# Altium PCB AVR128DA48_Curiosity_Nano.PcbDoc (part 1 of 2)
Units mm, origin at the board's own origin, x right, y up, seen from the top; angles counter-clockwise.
Board outline 83.82 x 20.32 mm, 4 copper layers (Top-Layer, Ground Plane, Power Plane, Bottom Layer), stack 1.59 mm thick; 66 components, 98 nets, 469 pads, 191 vias.
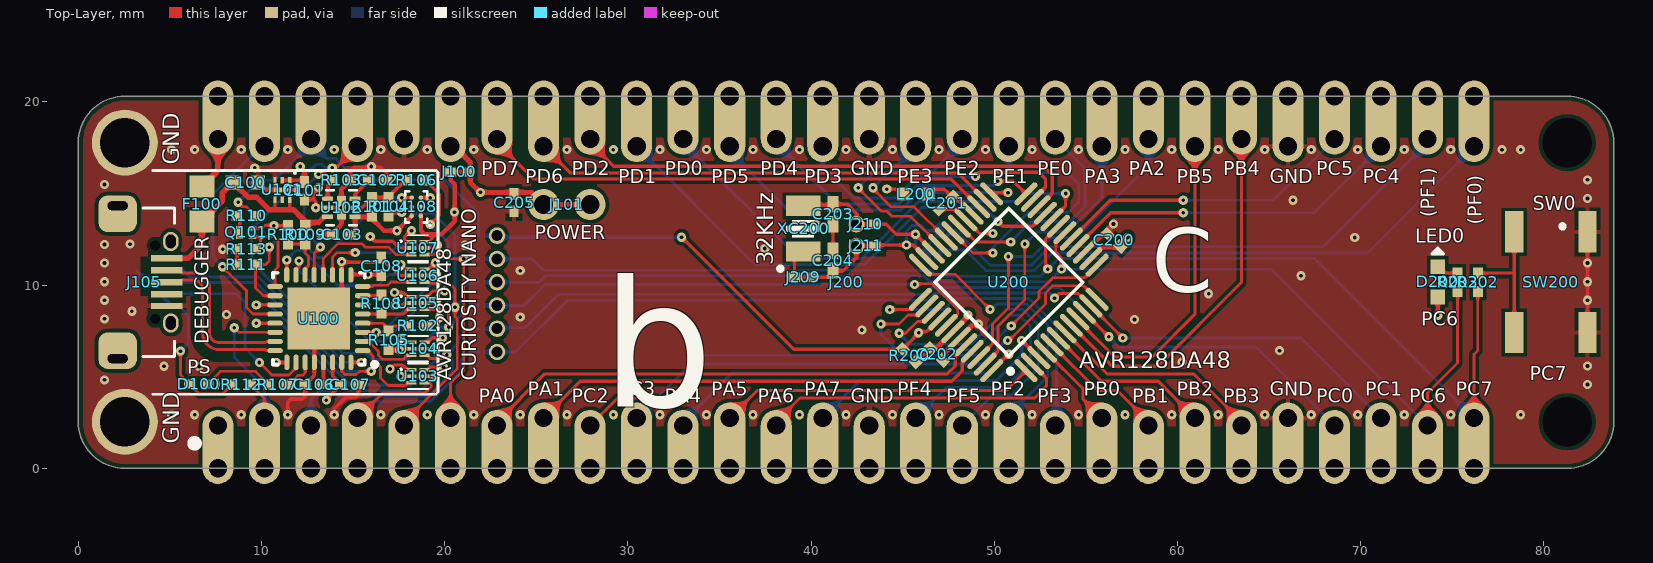
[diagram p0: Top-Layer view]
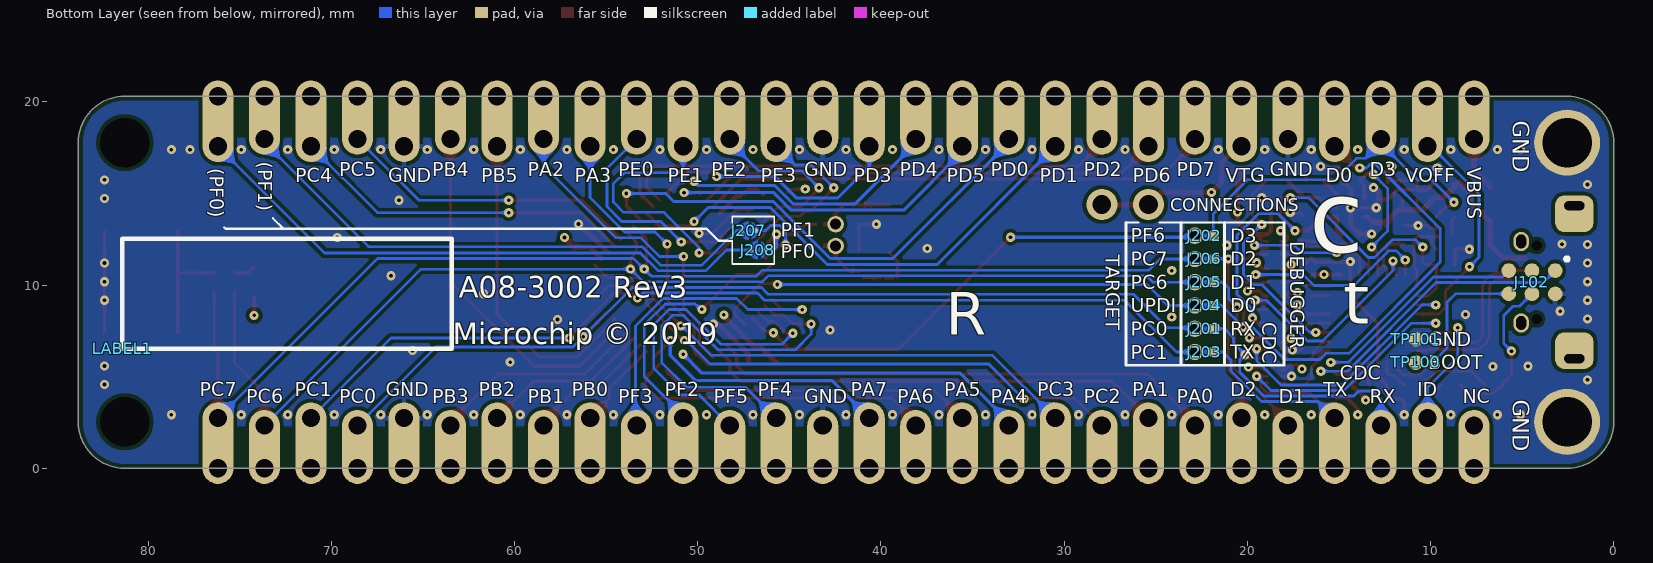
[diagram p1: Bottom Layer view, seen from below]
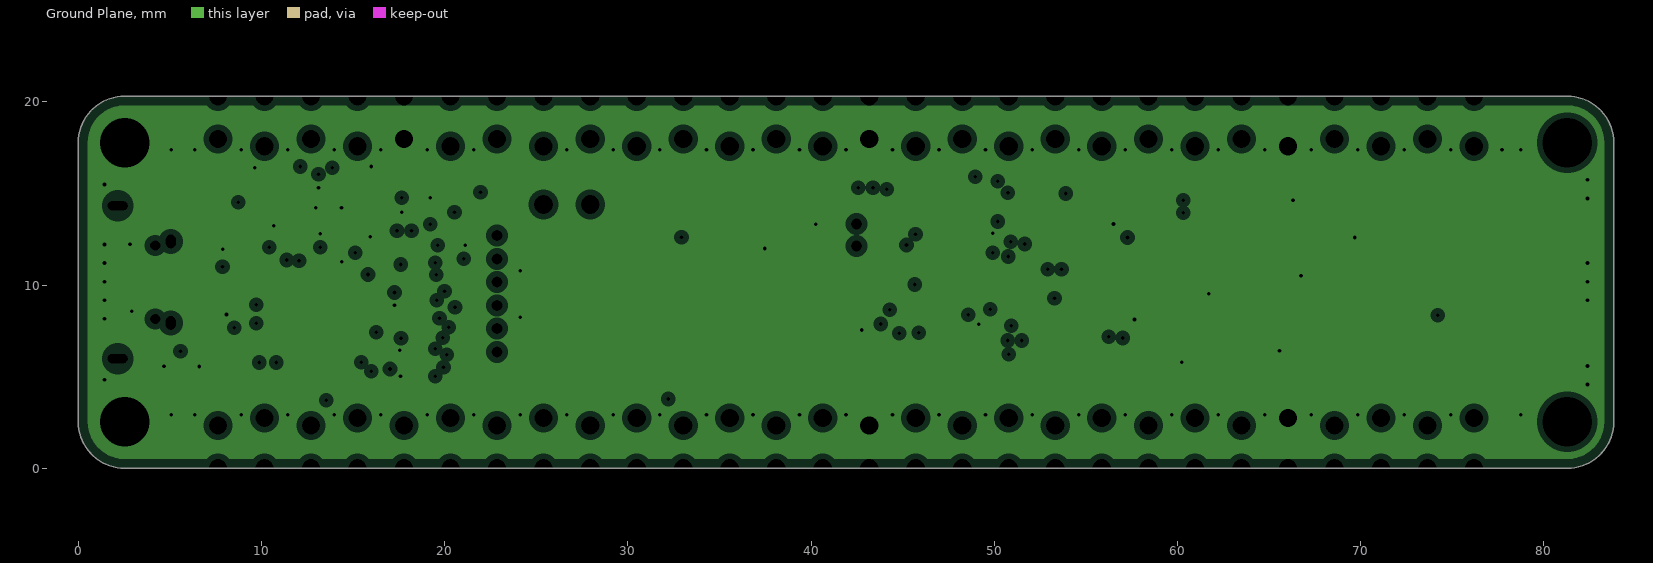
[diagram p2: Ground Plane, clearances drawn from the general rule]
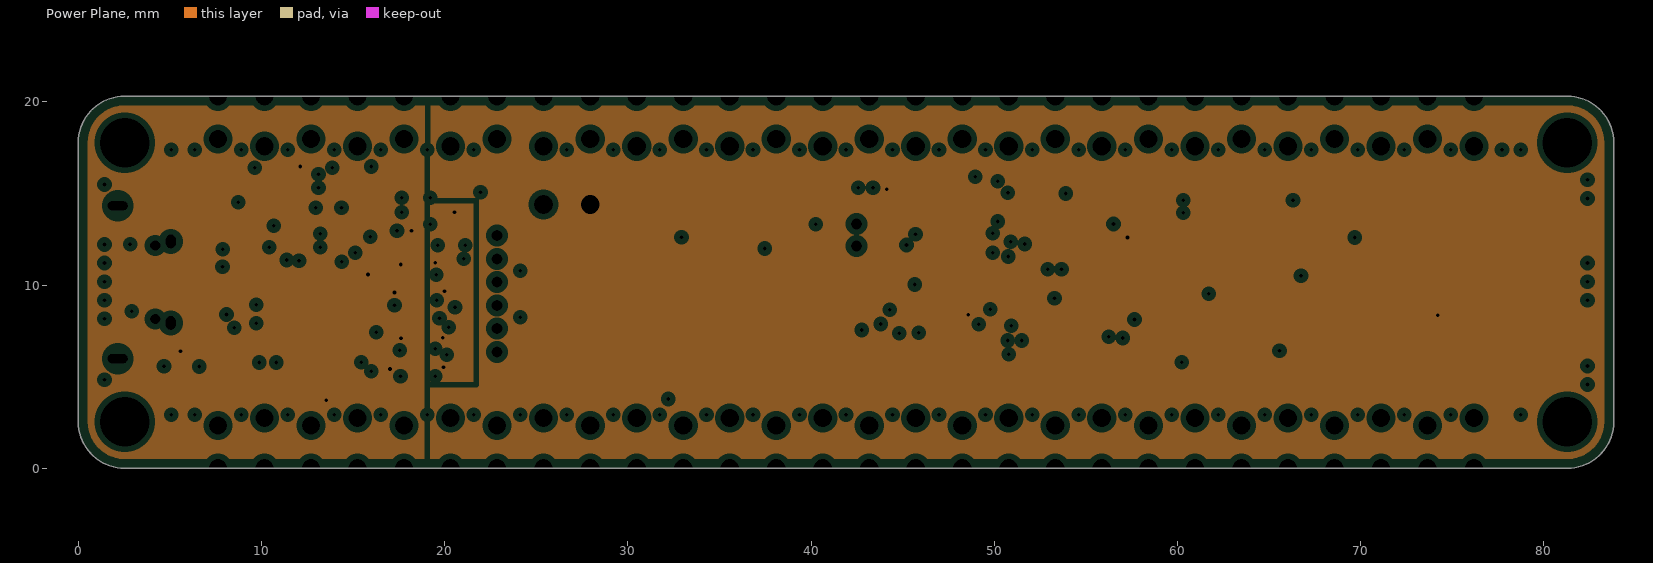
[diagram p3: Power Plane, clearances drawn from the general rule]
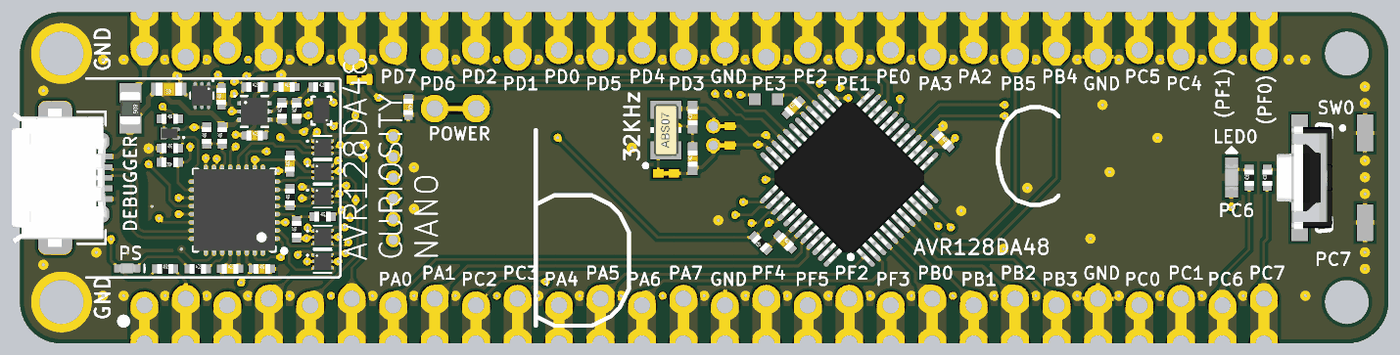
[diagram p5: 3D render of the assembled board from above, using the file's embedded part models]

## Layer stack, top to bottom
Top Solder: solder mask 0.0102, Solder Resist, Dk 3.5
Top-Layer: signal copper 0.035
Dielectric 1: prepreg 0.11, FR-4, Dk 4.2
Ground Plane: plane copper 0.035, net GND
Dielectric 3: core 1.23, Dk 4.2
Power Plane: plane copper 0.035, net (Multiple Nets)
Dielectric 4: prepreg 0.11, Dk 4.2
Bottom Layer: signal copper 0.035
Bottom Solder: solder mask 0.0102, Solder Resist, Dk 3.5

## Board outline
0,2.54 0,17.78 cw(c2.54,17.78) 2.54,20.32 81.28,20.32 cw(c81.28,17.78) 83.82,17.78 83.82,2.54 cw(c81.28,2.54) 81.28,0 2.54,0 cw(c2.54,2.54)

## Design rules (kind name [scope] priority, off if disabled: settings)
AcuteAngle [All] p1: minimum=8.00000000000000E+0001 checktracksonly=TRUE
AssemblyTestPointUsage [All] p1: valid=2 allowmultiple=TRUE
AssemblyTestpoint AssemblyTestpoint_1 [OnBottomLayer and IsComponent] p1: testpointundercomponent=TRUE minsize=0.8 maxsize=2 preferedsize=0.8 minholesize=0 maxholesize=1 preferedholesize=0.25 testpointgrid=0.025 usegrid=FALSE gridtolerance=0 allowsidebottom=TRUE minspacing=1.27 compbodyclearance=1.27
AssemblyTestpoint [All] p2: testpointundercomponent=TRUE minsize=0.8 maxsize=3 preferedsize=0.8 minholesize=0 maxholesize=1 preferedholesize=0.25 testpointgrid=0.025 usegrid=FALSE gridtolerance=0 allowsidebottom=TRUE minspacing=1.27
BoardOutlineClearance BoardOutlineClearance_edge_connector [InComponent('J200') OR InComponent('J201')] p1: gap=0 ignorepadtopadclearanceinfootprint=FALSE
BoardOutlineClearance BoardOutlineClearance_text_top_layer [IsText AND OnTopSilkscreen] p2: gap=0.25 ignorepadtopadclearanceinfootprint=FALSE
BoardOutlineClearance BoardOutlineClearance_FirstPinDot [IsArc AND OnTopSilkscreen] p3: gap=0 ignorepadtopadclearanceinfootprint=FALSE
BoardOutlineClearance [All] p4: gap=0.25 ignorepadtopadclearanceinfootprint=FALSE
Clearance Clearance_Via_in_Pad [IsVia AND (InNet('GND') OR  InNet('BOOT'))] p1: gap=0 ignorepadtopadclearanceinfootprint=FALSE
Clearance Clearance_Poly_Impedance [IsRegion vs InDifferentialPairClass('All Differential Pairs')] p2: gap=0.6 ignorepadtopadclearanceinfootprint=FALSE except(0: Arc-Hole Track-Hole SMDPad-Hole THPad-Hole Via-Hole Fill-Hole Poly-Hole Region-Hole Text-Hole)
Clearance Clearance_Poly [InPoly] p3: gap=0.2 ignorepadtopadclearanceinfootprint=FALSE
Clearance [All] p4: gap=0.15 ignorepadtopadclearanceinfootprint=FALSE
ComponentClearance ComponentClearance_BETWEEN_TESTPOINTS [InComponentClass('Testpoints') vs InComponentClass('Testpoints')] p1: gap=0 collisioncheckmode=3 verticalgap=0 showdistances=FALSE
ComponentClearance ComponentClearance_EDGE [InComponent('J200') or HasFootprint('AP8-01166')] p2: gap=0 collisioncheckmode=3 verticalgap=0 showdistances=FALSE
ComponentClearance ComponentClearance_LABEL [InComponent('LABEL1')] p3: gap=0 collisioncheckmode=3 verticalgap=0 showdistances=FALSE
ComponentClearance [All] p4: gap=0.254 collisioncheckmode=3 verticalgap=0.254 showdistances=TRUE
DiffPairsRouting [All] p1: maxlimit=0.22 minlimit=0.22 mostfreqgap=0.22 toplayer_minwidth=0.16 toplayer_maxwidth=0.16 toplayer_prefwidth=0.16 bottomlayer_minwidth=0.16 bottomlayer_maxwidth=0.16 bottomlayer_prefwidth=0.16 maxuncoupledlength=20
FabricationTestPointUsage TestPointUsage [All] p1: valid=2 allowmultiple=TRUE
FabricationTestpoint Testpoint [All] p1: side=2 testpointundercomponent=TRUE minsize=0.55 maxsize=3 preferedsize=0.8 minholesize=0 maxholesize=1 preferedholesize=0.25 testpointgrid=0 allowsidebottom=TRUE usegrid=FALSE gridtolerance=0 minspacing=1.27
HoleSize [All] p1: absolutevalues=TRUE maxlimit=10 minlimit=0.2 maxpercent=80.000 minpercent=20.000
HoleToHoleClearance HoleToHoleClearance_NPTH [(HoleDiameter > 0) And (PadIsPlated = 'False')] p1: gap=0.25 allowstackedmicrovias=TRUE
HoleToHoleClearance [All] p2: gap=0.3 allowstackedmicrovias=TRUE
MinimumAnnularRing [All] p1: minimumring=0.15
MinimumSolderMaskSliver [All] p1: minsoldermaskwidth=0.08
NetAntennae [Not IsTestpoint] p1: netantennaetolerance=0
PlaneClearance [All] p1: clearance=0.3
PlaneConnect PlaneConnect_VIA [IsVia OR HasPad('Free-666') OR HasPad('Free-EDGE')] p1: planeconnectstyle=Direct reliefexpansion=0.508 reliefentries=4 reliefconductorwidth=0.254 reliefairgap=0.254
PlaneConnect [All] p2: planeconnectstyle=Relief reliefexpansion=0.508 reliefentries=4 reliefconductorwidth=0.254 reliefairgap=0.254
PolygonConnect PolygonConnect_VIA [IsVia OR HasPad('Free-666') OR HasFootprint('AP8-00870')] p1: connectstyle=Direct reliefconductorwidth=0.254 reliefentries=4 polygonreliefangle="90 Angle" airgapwidth=0.254
PolygonConnect [All] p2: connectstyle=Relief reliefconductorwidth=0.254 reliefentries=4 polygonreliefangle="90 Angle" airgapwidth=0.2
RoutingVias [All] p1: holewidth=0.25 width=0.55 viastyle="Through Hole" minholewidth=0.2 minwidth=0.5 maxholewidth=0.5 maxwidth=1
SMDNeckDown [All] p1: percent=98.000
ShortCircuit ShortCircuit_NC_edge_connector [IsPad AND OnLayer('Multi-Layer') AND HasFootprint('AP8-01100') vs IsPad AND OnLayer('Multi-Layer') AND HasFootprint('AP8-01100')] p1: allowed=TRUE
ShortCircuit [All] p2: allowed=FALSE
SilkToSilkClearance SilkToSilkClearance_Text [IsText] p1: silktosilkclearance=0
SilkToSilkClearance [All] p2: silktosilkclearance=0.1
SilkToSolderMaskClearance SilkscreenOverComponentPads_Soldermask [All] p1: minsilkscreentomaskgap=0.12 clearancetoexposedcopper=FALSE
SilkToSolderMaskClearance SilkscreenOverComponentPads_Copper [All] p2: minsilkscreentomaskgap=0.2 clearancetoexposedcopper=TRUE
SolderMaskExpansion SolderMaskTenting [IsVia AND NOT (IsFabTestpoint OR IsAssyTestpoint)] p1: expansion=-1 istentingtop=FALSE
SolderMaskExpansion [All] p2: expansion=0.06 istentingtop=FALSE
ViasUnderSMD ViasUnderSMD_GND [InComponent('U102') And OnLayer('Top-Layer')] p1: allowed=TRUE
ViasUnderSMD ViasUnderSMD_Testpoint [InNet('BOOT') or InNet('GND')] p2: allowed=TRUE
ViasUnderSMD [All] p3: allowed=FALSE
Width Width_Power [InNetClass('Power')] p1: maxlimit=0.5 minlimit=0.175 preferedwidth=0.25
Width [All] p2: maxlimit=10 minlimit=0.15 preferedwidth=0.15
15 further rules are at their usual default settings.

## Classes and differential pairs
differential pair USBD: +USBD_P -USBD_N

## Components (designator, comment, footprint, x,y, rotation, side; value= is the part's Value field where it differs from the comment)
C100 "" AP1-00039 9.118,15.597 r180 top locked value=4.7uF
C101 "Farnell no: 1288200" AP1-00053 12.339,15.15 r90 top locked value=2.2uF
C102 "" AP1-00053 16.34,15.725 r0 top locked value=100n
C103 "" AP1-00053 14.37,12.75 r0 top locked value=2.2uF
C106 "" AP1-00053 12.865,4.575 r0 top locked value=1u
C107 "" AP1-00053 14.815,4.575 r0 top locked value=100n
C108 "" AP1-00053 16.54,11.025 r90 top locked value=100n
C200 "" AP1-00053 56.54,12.446 r315 top locked value=100n
C201 "" AP1-00053 47.371,14.478 r45 top locked value=100n
C202 "" AP1-00053 46.863,6.223 r315 top locked value=100n
C203 "" AP1-00001 41.196,13.874 r90 top locked value=12p
C204 "" AP1-00001 41.196,11.338 r90 top locked value=12p
C205 "" AP1-00053 23.79,14.51 r270 top locked value=2.2uF
D100 "" AP4-00160 6.571,4.6 r180 top locked value="GREEN LED"
D200 "" AP4-00169 74.221,10.181 r270 top locked value="YELLOW LED"
F100 "Farnell no: 1861197" AP2-00002 6.75,14.427 r270 top value=MC36213
J100 "" AP8-00595#1 20.795,16.18 r0 top net-tie value="Closed Link"
J101 "" AP8-01183 26.67,14.402 r0 top locked net-tie value="Closed Link 1x2 100mil header"
J102 "" AP8-00997 5.73,10.16 r0 bottom locked value="Testpoint Array"
J105 "" AP8-01099 2.15,10.16 r270 top locked value=MU-MB0142AB2-269
J200 "" AP8-01100 7.62,10.16 r0 top locked value="CNANO56-pin edge connector"
J201 "" AP8-01166 22.335,7.62 r0 bottom locked net-tie value="Closed Link"
J202 "" AP8-01166 22.335,12.7 r0 bottom locked net-tie value="Closed Link"
J203 "" AP8-01166 22.335,6.35 r0 bottom locked net-tie value="Closed Link"
J204 "" AP8-01166 22.335,8.89 r0 bottom locked net-tie value="Closed Link"
J205 "" AP8-01166 22.335,10.16 r0 bottom locked net-tie value="Closed Link"
J206 "" AP8-01166 22.335,11.43 r0 bottom locked net-tie value="Closed Link"
J207 "" AP9-00172 47.219,12.979 r0 bottom value=SOLDER-STRAP_OPEN
J208 "" AP9-00172 46.719,11.918 r0 bottom value=SOLDER-STRAP_OPEN
J209 "" AP8-00595#2 39.572,10.428 r180 top locked net-tie value="Closed Link"
J210 "" AP8-01166 43,13.326 r180 top net-tie value="Closed Link"
J211 "" AP8-01166 43,12.141 r180 top net-tie value="Closed Link"
L200 "" AP3-00005 45.716,14.976 r0 top value=BLM18PG471SN1
LABEL1 "" AP8-00317 81.425,6.525 r180 bottom locked value="Label PCBA"
Q101 "" AP5-00056 9.15,12.875 r180 top locked value=DMN65D8LFB
R100 "" AP2-00011 11.439,12.75 r90 top locked value=47k
R101 "" AP2-00011 16.04,14.275 r90 top locked value=47k
R102 "" AP2-00011 18.539,7.775 r0 top locked value=47k
R103 "" AP2-00011 14.365,15.725 r0 top locked value=47k
R104 "" AP2-00011 16.94,14.275 r90 top locked value=27k
R105 "" AP2-00011 16.94,6.999 r90 top locked value=47k
R106 "" AP2-00011 18.452,15.725 r0 top locked value=33k
R107 "" AP2-00011 10.89,4.575 r0 top locked value=1k
R108 "" AP2-00011 16.54,8.974 r90 top locked value=1k
R109 "" AP2-00011 12.389,12.75 r90 top locked value=47k
R110 "" AP2-00011 9.175,13.775 r0 top locked value=1k
R111 "" AP2-00011 9.175,11.112 r180 top locked value=47k
R112 "" AP2-00011 8.89,4.575 r0 top locked value=1k
R113 "" AP2-00011 9.175,11.968 r0 top locked value=47k
R200 "" AP2-00011 45.36,6.15 r135 top value=47k
R202 "" AP2-00011 76.405,10.156 r90 top value=1k
R203 "" AP2-00011 75.3,10.156 r90 top value=1k
SW200 "Rating: DC 12V 50mA / Max 0.1 ohm contact resistance" AP8-00137 80.391,10.16 r270 top locked value=TS604VM1-035CR
TP100 "PCB implemented component." AP8-00870 10.81,5.777 r90 bottom locked value="SMD Test point - 0.8mm"
TP101 "PCB implemented component." AP8-00870 10.81,7.047 r90 bottom locked value="SMD Test point - 0.8mm"
U100 "QFN32" AP6-00418 13.13,8.17 r90 top locked value=SAMD21E18A-MUT
U101 "" AP6-00481 11.139,15.2 r270 top locked value=MIC5528-3.3YMT
U102 "Marking code: AAR" AP6-00504 14.365,14.225 r0 top locked value=MIC5353
U103 "" AP6-00505 18.539,5.025 r0 top locked value=74LVC1T45FW4-7
U104 "" AP6-00505 18.539,6.525 r0 top locked value=74LVC1T45FW4-7
U105 "" AP6-00505 18.539,9.025 r0 top locked value=74LVC1T45FW4-7
U106 "" AP6-00505 18.539,10.525 r0 top locked value=74LVC1T45FW4-7
U107 "" AP6-00505 18.539,12.025 r0 top locked value=74LVC1T45FW4-7
U108 "" AP6-00513 18.452,14.275 r180 top locked value=MIC94163
U200 "" AP6-00357 50.8,10.16 r135 top locked value="AVR128DA48 TQFP"
XC200 "" AP7-00069 39.572,13.081 r90 top locked value=32.768kHz

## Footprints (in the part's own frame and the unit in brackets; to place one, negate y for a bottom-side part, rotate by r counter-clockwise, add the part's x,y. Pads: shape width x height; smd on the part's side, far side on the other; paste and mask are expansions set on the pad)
AP1-00001 [mm] "Standard 0402 SMD capacitor footprint"
  rect 0.9x0.6 smd: 1(-0.55,0) 2(0.55,0)
  body extent -0.5,-0.3 0.5,0.3, height 0.2
AP1-00039 [mil] "Capacitor 0603 Hight 0.8mm"
  rect 30x30 smd: 1(-27.5,0) 2(27.5,0)
  body extent -31,-16 32,16, height 12
AP1-00053 [mm] "Chip Capacitor, 2-Leads, Body 1.0x0.5mm, IPC High Density"
  rect 0.65x0.5 smd: 1(-0.475,0) 2(0.475,0)
  body extent -0.5,-0.3 0.5,0.3, height 0.2
AP2-00002 [mm]
  rect 1.2x1.35 smd: 1(-0.95,0) 2(0.95,0)
  body extent -1,-0.62 1,0.63, height 0.78
AP2-00011 [mm] "Chip Resistor, 2-Leads, Body 1,0x0,5mm, IPC High Density"
  rect 0.6x0.55 smd: 1(-0.5,0) 2(0.5,0)
  body extent -0.5,-0.3 0.5,0.3, height 0.2
AP3-00005 [mm]
  rect 0.7x0.7 smd: 1(-0.7,0) 2(0.7,0)
  body extent -0.83,-0.41 0.82,0.41, height 0.8
AP4-00160 [mm] "ROHM SML-P11 0402 LED"
  rect 0.6x0.5 smd: 1(-0.5,0) 2(0.5,0)
  silkscreen extent -1.14,-0.25 -1.05,0.25, body extent -0.5,-0.3 0.5,0.3, height 0.19
AP4-00169 [mm] "ROHM SML-D1x 0603 LED"
  rect 0.8x0.8 smd: 1(-0.825,0) 2(0.825,0)
  silkscreen extent -1.83,-0.3 -1.53,0.3, body extent -0.8,-0.4 0.8,0.4, height 0.54
AP5-00056 [mm] "DFN1006-3/SOT883, 3-Leads, Body 1,050x0,65mm, Pitch 0,35mm"
  oval 0.508x0.229 on Top Paste: 0(-0.4,0.25) 0(-0.4,-0.25)
  rect 0.4x0.25 smd paste-1: 1(-0.35,0.225) 2(-0.35,-0.225)
  rect 0.4x0.7 smd: 3(0.35,0)
  silkscreen extent -0.92,0.2 -0.83,0.3, body extent -0.5,-0.3 0.5,0.3, height 0.49
AP6-00357 [mm]
  oval 1.65x0.3 smd mask+0.05: 1(-4.075,2.75) 2(-4.075,2.25) 3(-4.075,1.75) 4(-4.075,1.25) 5(-4.075,0.75) 6(-4.075,0.25) 7(-4.075,-0.25) 8(-4.075,-0.75) 9(-4.075,-1.25) 10(-4.075,-1.75) 11(-4.075,-2.25) 12(-4.075,-2.75) 25(4.075,-2.75) 26(4.075,-2.25) 27(4.075,-1.75) 28(4.075,-1.25) 29(4.075,-0.75) 30(4.075,-0.25) 31(4.075,0.25) 32(4.075,0.75) 33(4.075,1.25) 34(4.075,1.75) 35(4.075,2.25) 36(4.075,2.75)
  oval 0.3x1.65 smd mask+0.05: 13(-2.75,-4.075) 14(-2.25,-4.075) 15(-1.75,-4.075) 16(-1.25,-4.075) 17(-0.75,-4.075) 18(-0.25,-4.075) 19(0.25,-4.075) 20(0.75,-4.075) 21(1.25,-4.075) 22(1.75,-4.075) 23(2.25,-4.075) 24(2.75,-4.075) 37(2.75,4.075) 38(2.25,4.075) 39(1.75,4.075) 40(1.25,4.075) 41(0.75,4.075) 42(0.25,4.075) 43(-0.25,4.075) 44(-0.75,4.075) 45(-1.25,4.075) 46(-1.75,4.075) 47(-2.25,4.075) 48(-2.75,4.075)
  silkscreen extent -3.62,-2.85 2.85,3.5, body extent -4.5,-4.5 4.5,4.5, height 1.45
AP6-00418 [mm] "MLF-32 solder foot print"
  oval 0.28x0.85 smd paste-0.03 mask+0: 1(-1.746,-2.39) 2(-1.246,-2.39) 3(-0.746,-2.39) 4(-0.246,-2.39) 5(0.254,-2.39) 6(0.754,-2.39) 7(1.254,-2.39) 8(1.754,-2.39) 17(1.754,2.39) 18(1.254,2.39) 19(0.754,2.39) 20(0.254,2.39) 21(-0.246,2.39) 22(-0.746,2.39) 23(-1.246,2.39) 24(-1.746,2.39)
  oval 0.85x0.28 smd paste-0.03 mask+0: 9(2.386,-1.746) 10(2.386,-1.246) 11(2.386,-0.746) 12(2.386,-0.246) 13(2.386,0.254) 14(2.386,0.754) 15(2.386,1.254) 16(2.386,1.754) 25(-2.383,1.746) 26(-2.383,1.246) 27(-2.383,0.746) 28(-2.383,0.246) 29(-2.383,-0.254) 30(-2.383,-0.754) 31(-2.383,-1.254) 32(-2.386,-1.75)
  rect 3.4x3.4 smd paste-1.7 mask+0: 33(0.004,0)
  silkscreen extent -2.62,-3.18 2.5,2.5, body extent -2.55,-2.55 2.55,2.55, height 1
AP6-00481 [mm] "6 Pin 1.2mm X 1.2mm Thin DFN"
  oval 0.483x0.203 on Top Paste: 0(-0.597,0.412) 0(-0.597,0) 0(-0.597,-0.412) 0(0.597,0.412) 0(0.597,0) 0(0.597,-0.412)
  rect 0.35x0.18 smd paste-0.09 mask+0.05: 1(-0.531,0.4) 2(-0.531,0) 3(-0.531,-0.4) 4(0.531,-0.4) 5(0.531,0) 6(0.531,0.4)
  rect 0.28x0.94 smd paste-0.02 mask+0.05: 7(0,0)
  silkscreen extent -0.97,0.64 -0.88,0.74, body extent -0.63,-0.62 0.63,0.63, height 0.6
AP6-00504 [mm] "MLF, 6-Leads, Body 1,60x1,60mm, Pitch 0,50mm, Thermal Pad 1,26x0,33mm, IPC High Density"
  rect 0.6x0.25 smd mask+0.05: 1(-0.75,0.5) 2(-0.75,0) 3(-0.75,-0.5) 4(0.75,-0.5) 5(0.75,0) 6(0.75,0.5)
  rect 0.5x1.26 smd paste-0.1 mask+0.05: 7(0,0)
  silkscreen extent -1.25,-0.95 0.82,1, body extent -0.87,-0.82 0.87,0.82, height 0.55
AP6-00505 [mm] "X2-DFN1010, 6-Leads, Body 1,05x1,05mm, Pitch 0,35mm, IPC High Density"
  oval 0.559x0.178 on Top Paste: 0(-0.375,-0.401) 0(-0.375,0) 0(-0.375,0.401) 0(0.375,-0.401) 0(0.375,0) 0(0.375,0.401)
  rect 0.55x0.2 smd paste-0.1: 1(-0.35,0.35) 2(-0.35,0) 3(-0.35,-0.35) 4(0.35,-0.35) 5(0.35,0) 6(0.35,0.35)
  silkscreen extent -0.97,-0.7 0.55,0.7, body extent -0.53,-0.53 0.53,0.53, height 0.4
AP6-00513 [mm] "BGA, 6-Leads, Body 1,00x1,50mmx0,80mm, Pitch 0,50mm"
  round 0.25 smd mask+0.05: A1(-0.25,0.5) A2(0.25,0.5) B1(-0.25,0) B2(0.25,0) C1(-0.25,-0.5) C2(0.25,-0.5)
  silkscreen extent -0.8,-0.85 0.6,1.05, body extent -0.5,-0.75 0.5,0.75, height 0.8
AP7-00069 [mm]
  rect 1.1x1.9 smd: 1(-1.25,0) 2(1.25,0)
  Top-Layer pour cut-out: -0.6,0.95 -0.6,-0.95 0.6,-0.95 0.6,0.95
  silkscreen extent -2.28,-0.95 0.47,1.35, body extent -1.6,-0.75 1.6,0.75, height 0.89
AP8-00137 [mm]
  rect 2.25x1 smd: 1(-2.75,2) 2(2.75,2) 3(-2.75,-2) 4(2.75,-2)
  silkscreen extent -3.15,0.54 -2.95,0.73, body extent -3.4,-3.21 3.4,3.22, height 3.47
AP8-00317 [mm] "Placement area for 18x6mm sticker"
  silkscreen extent 0,0 18,6
AP8-00595#1 [mm]
  rect 0.65x0.5 smd paste-1: 1(-0.475,0) 2(0.475,0)
  Top-Layer lines w0.254: -0.175,0 0.2,0
AP8-00595#2 [mm]
  rect 0.65x0.5 smd paste-2: 1(-0.475,0) 2(0.475,0)
  Top-Layer lines w0.254: 0.2,0 -0.175,0
AP8-00870 [mil] "TP_SMT_.8mm"
  round 31.5 smd paste-39.37: 1(0,0)
AP8-00997 [mm] "SMT test point array 2x5 0.8mm, Pitch 1.27 mm"
  round 0.8 smd paste-1: 1(-2.54,-0.635) 2(-2.54,0.635) 3(-1.27,-0.635) 4(-1.27,0.635) 5(0,-0.635) 6(0,0.635)
  silkscreen extent -3.28,-1.37 -3.07,-1.17
AP8-01099 [mm] "Micro USB AB connector from Allen Creations. Signals surface mount, shield DIP"
  rrect52% 2x2.1 on Top Paste: 0(-3.69,0) 0(3.69,0)
  rrect100% 1.05x0.84 on Top Paste: 0(-2.225,2.9) 0(2.225,2.9)
  rect 0.35x1.7 smd: 1(-1.3,2.68) 2(-0.65,2.68) 3(0,2.68) 4(0.65,2.68) 5(1.3,2.68)
  rrect52% 2x2.1 hole 0.5 slot 1.1 at 90 deg copper offset 0.437,0: 6(-4.175,0)
  rrect52% 2x2.1 hole 0.5 slot 1.1 at 90 deg copper offset -0.437,0: 7(4.175,0)
  rrect100% 1.05x0.84 hole 0.54 slot 0.75 at 0 deg: 8(-2.225,2.9) 9(2.225,2.9)
  round 0 hole 0.55 unplated: 10(-2,2.05) 11(2,2.05)
  silkscreen extent -4.05,1.38 4.05,3.1, body extent -4.32,-2.65 4.33,3.25, height 2.78
AP8-01100 [mil] "56-pin Header staggered with castellations (for CNANO)"
  round 75 on Top Solder: 0(0,-400) 0(0,400) 0(100,-400) 0(100,400) 0(200,-400) 0(200,400) 0(300,-400) 0(300,400) 0(400,-400) 0(400,400) 0(500,-400) 0(500,400) 0(600,-400) 0(600,400) 0(700,-400) 0(700,400) 0(800,-400) 0(800,400) 0(900,-400) 0(900,400) 0(1000,-400) 0(1000,400) 0(1100,-400) 0(1100,400) 0(1200,-400) 0(1200,400) 0(1300,-400) 0(1300,400) 0(1400,-400) 0(1400,400) 0(1500,-400) 0(1500,400) 0(1600,-400) 0(1600,400) 0(1700,-400) 0(1700,400) 0(1800,-400) 0(1800,400) 0(1900,-400) 0(1900,400) 0(2000,-400) 0(2000,400) 0(2100,-400) 0(2100,400) 0(2200,-400) 0(2200,400) 0(2300,-400) 0(2300,400) 0(2400,-400) 0(2400,400) 0(2500,-400) 0(2500,400) 0(2600,-400) 0(2600,400) 0(2700,-400) 0(2700,400)
  oval 67x155 hole 39.37 copper offset 0,44 mask-20: 1(0,-400) 3(200,-400) 5(400,-400) 7(600,-400) 9(800,-400) 11(1000,-400) 13(1200,-400) 15(1400,-400) 17(1600,-400) 19(1800,-400) 21(2000,-400) 23(2200,-400) 25(2400,-400) 27(2600,-400)
  round 67 hole 39.37 mask+3.94: 1(0,-308) 2(100,-292) 3(200,-308) 4(300,-292) 5(400,-308) 6(500,-292) 7(600,-308) 8(700,-292) 9(800,-308) 10(900,-292) 11(1000,-308) 12(1100,-292) 13(1200,-308) 14(1300,-292) 15(1400,-308) 16(1500,-292) 17(1600,-308) 18(1700,-292) 19(1800,-308) 20(1900,-292) 21(2000,-308) 22(2100,-292) 23(2200,-308) 24(2300,-292) 25(2400,-308) 26(2500,-292) 27(2600,-308) 28(2700,-292) 29(2700,292) 30(2600,308) 31(2500,292) 32(2400,308) 33(2300,292) 34(2200,308) 35(2100,292) 36(2000,308) 37(1900,292) 38(1800,308) 39(1700,292) 40(1600,308) 41(1500,292) 42(1400,308) 43(1300,292) 44(1200,308) 45(1100,292) 46(1000,308) 47(900,292) 48(800,308) 49(700,292) 50(600,308) 51(500,292) 52(400,308) 53(300,292) 54(200,308) 55(100,292) 56(0,308)
  oval 67x171 hole 39.37 copper offset 0,52 mask-20: 2(100,-400) 4(300,-400) 6(500,-400) 8(700,-400) 10(900,-400) 12(1100,-400) 14(1300,-400) 16(1500,-400) 18(1700,-400) 20(1900,-400) 22(2100,-400) 24(2300,-400) 26(2500,-400) 28(2700,-400)
  oval 67x171 hole 39.37 copper offset 0,-52 mask-20: 29(2700,400) 31(2500,400) 33(2300,400) 35(2100,400) 37(1900,400) 39(1700,400) 41(1500,400) 43(1300,400) 45(1100,400) 47(900,400) 49(700,400) 51(500,400) 53(300,400) 55(100,400)
  oval 67x155 hole 39.37 copper offset 0,-44 mask-20: 30(2600,400) 32(2400,400) 34(2200,400) 36(2000,400) 38(1800,400) 40(1600,400) 42(1400,400) 44(1200,400) 46(1000,400) 48(800,400) 50(600,400) 52(400,400) 54(200,400) 56(0,400)
  Multi-Layer pour cut-out: -40,-310 -40,-450 2740,-450 2740,-310
  Multi-Layer pour cut-out: 2740,310 2740,450 -40,450 -40,310
AP8-01166 [mm] "Cut-Strap 0402 with hole"
  rect 0.65x0.5 smd paste-1: 1(-0.475,0)
  round 0.9 hole 0.6 paste-1: 2(0.525,0)
  Top-Layer region: -0.175,0.125 0.175,0.125 0.175,-0.125 -0.175,-0.125
AP8-01183 [mm] "closed link, 100-mil 1 x 2 pin header footprint"
  round 1.7 hole 1.02: 1(-1.27,0) 2(1.27,0)
  Top-Layer lines w0.3: -1.27,0 1.27,0
AP9-00172 [mm]
  round 0.25 smd paste-4 mask-2: 1(-0.375,0) 2(0.375,0)
  round 1.05 on Bottom Solder: 5(0,0)
  Top-Layer region: 0,-0.5 0.217,-0.45 0.391,-0.312 0.487,-0.111 0.487,0.111 0.391,0.312 0.217,0.45 0,0.5 0,0.5 0,0.325 0.25,0.075 0.25,-0.075 0,-0.325
  Top-Layer region: -0.175,-0.468 -0.373,-0.333 -0.485,-0.12 -0.485,0.12 -0.373,0.333 -0.175,0.468 -0.175,0.468 -0.175,0.468 -0.175,0.25 0.075,0 0.075,0 -0.175,-0.25
  body extent -0.25,-0.25 0.25,0.25, height 0.45

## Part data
C100: library part A01-0377, "Ceramic capacitor, SMD 0603, X5R, 10V, 10% (de31036)", Manufacturer="WALSIN Technology Corporation", MPN=0603X475K100CT, TemperatureRange="-55 - +85 deg C", Tolerance=10%
C101: library part A01-0300, "Ceramic capacitor, SMD 0402, X5R, 6.3V, +/-20%", Manufacturer=Kemet, MPN=C0402C225M9PAC, TemperatureRange="-55Â°C to +85Â°C", Tolerance=Â±20%
C102 C107 C108 C200 C201 C202: library part A01-0246, "Ceramic capacitor, SMD 0402, X7R, 16V, +/-10%", Manufacturer=Kemet, MPN=C0402C104K4RACTU, TemperatureRange="-55 - +125 deg C", Tolerance="16V, +/-10%"
C103 C205: library part A01-0493, "CAP CER 2.2UF 10V 10% X5R 0402", Manufacturer=TDK, MPN=C1005X5R1A225K, TemperatureRange="-55 to 85C", Tolerance=+/-10%
C106: library part A01-0286, "Ceramic capacitor, SMD 0402, X5R, 6.3V, +/-10% (de26942)", Manufacturer=Kemet, MPN=C0402C105K9PAC, TemperatureRange="-55 to 85 deg C", Tolerance=+/-10%
C203 C204: library part A01-0016, "Ceramic capacitor, SMD 0402, NP0, 50V, +/-5%", Manufacturer=Kemet, MPN=C0402C120J5GAC7867, TemperatureRange="-55 - +125 deg C", Tolerance="50V, +/-5%"
D100: library part A10-0213, "LED, SMD 0402, Green, Wave length=569nm, 2.1mcd @ (1mA, 1.9Vf)rohm", Manufacturer=ROHM, MPN=SML-P12MTT86R, TemperatureRange="-40 to +85"
D200: library part A10-0218, "LED, SMD 0603, Yellow, Wave length=590nm, 100mcd @ (20mA, 2.2Vf) rohm", Manufacturer=ROHM, MPN=SML-D12Y1WT86, TemperatureRange="-40 to +85"
F100: library part A02-0622, "Resetable PTC fuse, Ih = 0.5A, It = 1.0A, 0805 package", Manufacturer=Multicomp, MPN=MC36213, TemperatureRange="-40°C to + 85°C"
J100 J209: library part A08-1454, "Closed Link 0402"
J101: library part A08-3029, "Closed Link with w/hole for 1x2 100mil header"
J102: library part A08-2568, "10-pin Testpoint Array, 0.8mm Pad, 1.27mm Pitch"
J105: library part A08-2839, "USB micro AB, Surface mount signals and DIP shield", Manufacturer="Allen Creations Corp.", MPN=MU-MB0142AB2-269, TemperatureRange="-30Â°C to +80Â°C"
J200: library part A08-2840, "Curiosity Nano 56-pin edge connector with castellations, 100-mil pitch."
J201 J202 J203 J204 J205 J206 J210 J211: library part A08-2981, "Closed Link 0402 w/50mil hole"
J207 J208: library part A08-2866, "1x1mm, Round Strap, Open, no frame"
L200: library part A03-0035, "SMD RF inductor 0603. Z=470Ohm (@100MHz), Max R(dc)=0.20Ohm, Max current=1A", Manufacturer=Murata, MPN=BLM18PG471SN1, TemperatureRange=-55
LABEL1: library part A09-0611, "PCBA identification label PP Top White Gloss", Manufacturer="ACT Logimark AS", MPN=505462
Q101: library part A05-0180, "N-channel MOSFET, DFN1006-3 (SOT883), 60V, 330mA, 4Ohm", Manufacturer="Diodes Incorporated", MPN=DMN65D8LFB-7, TemperatureRange="-55Â°C to +150Â°C"
R100 R101 R102 R103 R105 R109 R111 R113 R200: library part A02-0252, "Thick film resistor, SMD 0402, 1/16W, 1%", Manufacturer=KOA, MPN=RK73H1ETTP4702F, TemperatureRange="-55 - +125 deg C", Tolerance="1 %"
R104: library part A02-0246, "Thick film resistor, SMD 0402, 1/16W, 1%", Manufacturer=Yageo, MPN=RC0402FR-0727KL, TemperatureRange="-55 - +125 deg C", Tolerance="1 %"
R106: library part A02-0248, "Thick film resistor, SMD 0402, 1/16W, 1%", Manufacturer="ASJ Holdings", MPN=CR10-3302-FK, TemperatureRange="-55 - +125 deg C", Tolerance="1 %"
R107 R108 R110 R112 R202 R203: library part A02-0212, "Thick film resistor, SMD 0402, 1/16W, 1%", Manufacturer="ASJ Holdings", MPN=CR10-1001-FK, TemperatureRange="-55 - +125 deg C", Tolerance="1 %"
SW200: library part A08-2830, "SWITCH, SMD, 260gf, 6.4mm X 6.2mm", Manufacturer="Dailywell Electronics Co.LTD", MPN=TS604VM1-035CR-R, TemperatureRange="-40 - +85 deg C"
TP100 TP101: library part A08-2176, "SMD Test point - 0.8mm"
U100: library part A06-1205, "32-bit RISC MCU 32pin", Manufacturer=Microchip, MPN=ATSAMD21E18A-MUT, TemperatureRange="-40Â°C to +85Â°C"
U101: library part A06-1475, "LDO 3.3V 0.5A 6TDFN", Manufacturer=Microchip, MPN=MIC5528-3.3YMT-T5, TemperatureRange="-40Â°C ~ 125Â°C"
U102: library part A06-1578, "500mA Ultra Low Dropout LDO regulator, 2% accuracy, 1.6x1.6mm MLF", Manufacturer=Microchip, MPN=MIC5353YMT-TR, TemperatureRange="-40Â°C to +125Â°C"
U103 U104 U105 U106 U107: library part A06-1580, "Single-Bit Dual-Supply Transceive, 1.65-5.5 Translation and 3-State Outputs", Manufacturer="Diodes Incorporated", MPN=74LVC1T45FW4-7, TemperatureRange="-40C - 125C"
U108: library part A06-1613, "Loadswitch, Rds(on) = 14.5mohm, 1.0mm x 1.5mm WLCSP, reverse blocking", Manufacturer=Microchip, MPN=MIC94163YCS-TR, TemperatureRange="-40Â°C to +125Â°C"
U200: library part A06-1684, "8-bit RISC MCU, 128K Flash, 48pin TQFP, 7x7mm, 0.5m pitch package", Manufacturer=Microchip, MPN=AVR128DA48T-I/PT, TemperatureRange="-40°C to +125°C"
XC200: library part A07-0170, "Crystal, 32.768kHz, CL=9.0pF, ESR=70kOhm, SMD  LxW=3.2 x 1.5mm, 20ppm", Manufacturer=Abracon, MPN=ABS07-32.768kHz-9-T, TemperatureRange="-40°C to + 85°C", Tolerance=20ppm

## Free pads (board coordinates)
  round 0 hole 2.7 unplated paste-2.6: 0(81.28,2.54) 0(81.28,17.78)
  round 3.6 hole 2.7 paste-2.6: 666(2.54,2.54) 666(2.54,17.78)

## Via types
v1: diameter 0.5, hole 0.2, Top-Layer to Bottom Layer, 187 vias
v2: diameter 0.5, hole 0.2, Top-Layer to Bottom Layer, tented both sides, 2 vias
v3: diameter 0.5, hole 0.2, Top-Layer to Bottom Layer, tented top, 2 vias

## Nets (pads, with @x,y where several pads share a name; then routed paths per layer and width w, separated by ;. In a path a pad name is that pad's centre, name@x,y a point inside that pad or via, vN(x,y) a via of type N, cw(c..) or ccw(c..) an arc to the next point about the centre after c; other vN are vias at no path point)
AVDD: C201.2 L200.2 U200.28 | length 3
  Top-Layer w0.175: L200.2@46.422,14.92 46.742,15.24 47.281,15.24 C201.2@47.707,14.814 ; C201.2@47.742,14.849 C201.2@47.879,14.849
  Top-Layer w0.27: C201.2@47.879,14.849 U200.28@48.802,13.925
BOOT: TP100.1 U100.25 | length 0.6
  Top-Layer w0.2: v3(10.81,5.777) U100.25@11.393,5.777
CDC_RX: J200.3 J201.1 U104.4 | length 14.8
  Top-Layer w0.15: U104.4@18.889,6.175 19.031,6.175 19.206,6 19.915,6 v1(20.115,6.2)
  Bottom Layer w0.15: J200.3@12.7,2.54 12.7,3.785 13.14,4.225 13.915,4.225 14.19,3.95 19.096,3.95 20.415,5.269 20.415,5.9 v1(20.115,6.2) 20.752,6.837 20.752,7.117 21.255,7.62 J201.1@21.86,7.62 ; J201.1@21.86,7.61 J201.1@21.91,7.61
CDC_RX_CTRL: U100.19 U104.5 | length 14.4
  Top-Layer w0.15: v1(9.715,8.925) U100.19@10.74,8.924 ; U104.5@18.889,6.525 v1(19.49,6.525)
  Bottom Layer w0.15: v1(9.715,8.925) 10.47,8.925 14.845,4.55 18.165,4.55 19.49,5.875 v1(19.49,6.525)
CDC_TX: J200.4 J203.1 U103.4 | length 13.7
  Top-Layer w0.15: J200.4@15.24,2.743 16.622,4.125 18.941,4.125 19.265,4.449 19.265,4.573 19.177,4.661 18.903,4.661 U103.4@18.889,4.675
  Bottom Layer w0.15: J200.4@15.24,2.743 16.147,3.65 19.22,3.65 20.89,5.32 20.89,5.9 21.34,6.35 J203.1@21.86,6.35
CDC_TX_CTRL: U100.21 U103.5 | length 13.2
  Top-Layer w0.15: v1(9.715,7.924) U100.21@10.74,7.924 ; U103.5@18.889,5.025 v1(19.49,5.025)
  Bottom Layer w0.15: v1@9.715,7.925 11.046,7.925 14.721,4.25 18.715,4.25 v1(19.49,5.025)
DAC: R106.2 U100.3 | length 12.1
  Top-Layer w0.15: U100.3@15.52,7.424 v1(16.264,7.424) ; R106.2@18.952,15.725 19.714,14.963 19.714,13.816 v1(19.215,13.317) v1@19.215,13.267
  Bottom Layer w0.15: v1(16.264,7.424) 16.589,7.424 19.189,10.024 19.664,10.024 20.215,10.575 20.215,12.317 v1(19.215,13.317)
DBG0: J200.53 J204.1 U105.4 | length 27.6
  Top-Layer w0.15: v1(13.865,16.4) 14.063,16.4 J200.53@15.24,17.577 ; U105.4@18.889,8.675 19.987,8.675 20.215,8.447 v1(20.215,7.7)
  Bottom Layer w0.15: v1(13.865,16.4) 13.49,16.4 13.29,16.6 12.987,16.6 9.473,13.086 9.473,11.248 14.446,6.275 15.71,6.275 16.044,5.941 17.956,5.941 19.715,7.7 v1(20.215,7.7) 21.405,8.89 J204.1@21.86,8.89
DBG0_CTRL: U100.15 U105.5 | length 12.1
  Top-Layer w0.15: U100.15@11.876,10.556 11.876,10.861 12.051,11.036 v1(12.051,11.325) ; U105.5@18.889,9.025 19.332,9.025 19.482,9.175 v1(19.564,9.175)
  Bottom Layer w0.15: v1(12.051,11.325) 12.051,10.796 15.903,6.944 16.713,6.944 18.943,9.175 v1(19.564,9.175)
DBG1: J200.5 J205.1 U106.4 | length 12.6
  Top-Layer w0.15: J200.5@17.78,2.54 20.69,5.45 20.69,8.15 20.565,8.275 v1(20.565,8.79) 20.565,9.794 20.209,10.15 19.786,10.15 19.736,10.1 19.244,10.1 19.194,10.15 18.914,10.15 U106.4@18.889,10.175
  Bottom Layer w0.15: v1(20.565,8.79) 21.008,9.233 21.008,9.825 21.343,10.16 J205.1@21.86,10.16
DBG1_CTRL: U100.16 U106.5 | length 10.9
  Top-Layer w0.15: U100.16@11.376,10.556 v1(11.376,11.375) ; U106.5@18.889,10.525 v1@19.514,10.525
  Bottom Layer w0.15: v1(11.376,11.375) 11.881,11.88 12.26,11.88 14.165,9.975 16.365,9.975 16.965,10.575 v1(19.539,10.575)
DBG2: J200.6 J206.1 U107.4 | length 12.3
  Top-Layer w0.15: U107.4@18.889,11.675 19.315,11.675 19.34,11.7 19.715,11.7 19.98,11.435 v1@21.015,11.435 ; J200.6@20.32,2.54 20.32,4.656 21.04,5.376 v1(21.04,11.435)
  Bottom Layer w0.15: v1@21.015,11.435 v1(21.04,11.435) J206.1@21.86,11.435
DBG2_CTRL: U100.11 U107.5 | length 8
  Top-Layer w0.15: U100.11@13.876,10.556 13.876,11.537 14.114,11.775 v1(15.115,11.775) ; U107.5@18.889,12.025 19.34,12.025 19.49,12.175 v1(19.614,12.175) v1@19.714,12.175
  Bottom Layer w0.15: v1(15.115,11.775) 17.031,11.775 17.431,12.175 v1(19.614,12.175) v1@19.714,12.175
DBG2_GPIO: U100.12 U107.3 | length 6.3
  Top-Layer w0.15: U100.12@13.376,10.556 13.376,11.461 14.182,12.267 15.473,12.267 15.665,12.075 16.939,12.075 17.339,11.675 U107.3@18.189,11.675
DBG3: J200.54 J202.1 R110.2 | length 18.6
  Top-Layer w0.15: v1(8.725,14.525) 8.975,14.275 9.175,14.275 R110.2@9.674,13.776 ; R110.2@9.674,13.7 R110.2@9.674,13.776 ; R110.2@9.675,13.775 R110.2@9.674,13.776
  Bottom Layer w0.15: v1(8.725,14.525) 9.925,15.725 10.693,15.725 11.918,16.95 11.925,16.95 12.7,17.725 12.7,17.78 13.555,16.925 13.772,16.925 13.773,16.924 14.041,16.924 15.212,15.753 19.977,15.753 ; 19.977,15.778 21.86,13.895 ; J202.1@21.86,12.7 21.86,13.87
DBG3_CTRL: Q101.1 R113.2 U100.17 | length 4.9
  Top-Layer w0.15: Q101.1@9.5,12.65 9.95,12.65 ; R113.2@9.675,11.968 9.95,12.243 9.95,12.65 ; U100.17@10.74,9.924 10.74,10.825 10.901,10.986 10.901,12.451 10.702,12.65 9.95,12.65
GND: C100.1 C101.1 C102.2 C103.1 C106.1 C107.2 C108.2 C200.1 C201.1 C202.2 C203.1 C204.2 C205.2 J102.2 J105.5 J200.15 J200.24 J200.33 J200.42 J200.52 pad.666 Q101.2 R100.2 R103.2 R104.1 R105.1 R111.2 R113.1 SW200.1 SW200.2 TP101.1 U100.10 U100.28 U100.33 U101.3 U101.7 U102.2 U102.7 U103.2 U104.2 U105.2 U106.2 U107.2 U108.C1 U200.15 U200.29 U200.43 | length 57.3
  Top-Layer w0.15: Q101.2@9.5,13.1 10.035,13.1 10.21,13.275 10.65,13.275 v1(10.675,13.25) R100.2@11.439,13.25 ; v1(40.253,13.324) C203.1@41.196,13.324 C204.2@41.196,11.888 ; U200.29@48.449,13.572 49.195,12.826 v1(49.927,12.826)
  Top-Layer w0.175: v1(7.879,11.959) 7.888,11.968 R113.1@8.675,11.968 R111.2@8.675,11.112 ; U101.3@10.739,15.725 10.739,15.2 U101.7@11.139,15.2 ; v1(12.965,14.225) U102.2@13.615,14.225 v1(14.365,14.225) ; 14.865,16.275 15.026,16.436 16.517,16.436 16.815,16.138 C102.2@16.815,15.725 ; v1(15.94,12.65) 16.19,12.4 17.17,12.4 17.545,12.025 U107.2@18.189,12.025 ; C108.2@16.518,11.5 17.493,10.525 U106.2@18.189,10.525 ; R104.1@16.94,13.775 17.14,13.975 v1(17.659,13.975) ; R105.1@17.015,6.525 17.09,6.45 v1(17.54,6.45) 17.615,6.525 U104.2@18.189,6.525 ; v1(17.264,8.9) 17.677,8.9 17.803,9.025 U105.2@18.189,9.025 ; v1(17.59,5.025) U103.2@18.189,5.025 ; C201.1@47.024,14.131 C201.1@47.035,14.131 ; C201.1@47.035,14.142 47.879,14.142 U200.29@48.449,13.572 ; C200.1@55.932,12.817 C200.1@56.017,12.817 ; v1@56.388,13.188 56.515,13.315 v1(56.515,13.335) ; SW200.2@82.391,7.41 v1(82.391,9.173) v1(82.391,10.189) v1(82.391,11.205) SW200.1@82.391,12.91
  Top-Layer w0.2: U101.7@11.139,15.2 11.814,15.2 C101.1@12.339,14.675 12.84,14.675 ; v1(11.43,2.921) 11.43,3.615 11.6,3.785 12.225,3.785 12.39,3.95 C106.1@12.39,4.575 12.884,5.069 U100.28@12.884,5.787 12.884,7.909 U100.33@13.139,8.164 ; v1(12.965,14.225) 12.965,14.55 12.84,14.675 ; v1(13.115,15.325) 12.84,15.05 12.84,14.675 ; U100.33@13.149,8.174 14.376,9.401 U100.10@14.376,10.556 14.376,11.112 14.523,11.259 16.277,11.259 C108.2@16.518,11.5 ; v1(13.97,2.921) 13.97,3.255 14.559,3.844 15.106,3.844 15.29,4.028 C107.2@15.29,4.575 ; R103.2@14.865,15.725 14.865,16.275 ; U108.C1@18.702,14.775 v1(19.215,14.775)
  Top-Layer w0.25: C100.1@9.816,15.597 10.214,15.2 U101.7@10.739,15.2 ; v1@13.165,12.8 C103.1@13.895,12.8 ; C103.1@13.895,12.75 13.895,12.847 14.365,13.317 v1(14.365,14.225) 14.365,15.225 R103.2@14.865,15.725
  Top-Layer w0.27: C202.2@47.234,5.852 47.234,6.241 U200.43@48.095,7.102 48.103,7.102 48.832,7.83 49.105,7.83 v1(49.149,7.874) ; U200.15@54.919,11.804 C200.1@55.932,12.817 ; C200.1@56.017,12.817 v1@56.388,13.188
  other v1: 5.08,2.921 6.35,2.921 8.89,2.921 16.51,2.921 19.05,2.921 21.59,2.921 24.13,2.921 26.67,2.921 29.21,2.921 31.75,2.921 34.29,2.921 36.83,2.921 39.37,2.921 41.91,2.921 44.45,2.921 46.99,2.921 49.53,2.921 52.07,2.921 54.61,2.921 57.15,2.921 59.69,2.921 62.23,2.921 64.77,2.921 67.31,2.921 69.85,2.921 72.39,2.921 74.93,2.921 78.74,2.921 82.391,4.572 1.429,4.826 4.675,5.575 82.391,5.588 60.246,5.796 65.575,6.425 42.775,7.55 57.658,8.128 1.429,8.157 24.13,8.255 2.925,8.575 1.429,9.173 61.71,9.534 1.429,10.189 66.751,10.51 24.13,10.795 1.429,11.205 14.373,11.284 37.475,12 21.115,12.175 1.429,12.221 2.825,12.238 69.685,12.6 13.215,12.8 66.314,14.632 82.391,14.732 1.429,15.494 82.391,15.748 9.63,16.4 16,16.475 5.08,17.399 6.35,17.399 8.89,17.399 11.43,17.399 13.97,17.399 16.51,17.399 19.05,17.399 21.59,17.399 26.67,17.399 29.21,17.399 31.75,17.399 34.29,17.399 36.83,17.399 39.37,17.399 41.91,17.399 44.45,17.399 46.99,17.399 49.53,17.399 52.07,17.399 54.61,17.399 57.15,17.399 59.69,17.399 62.23,17.399 64.77,17.399 67.31,17.399 69.85,17.399 72.39,17.399 74.93,17.399 77.724,17.399 78.74,17.399
  other v2: 6.596,5.56 8.088,8.4
ID_SYS: J200.2 R112.2 U100.22 | length 10.5
  Top-Layer w0.15: v1(8.515,7.675) 8.766,7.424 U100.22@10.74,7.424 ; R112.2@9.39,4.575 10.16,3.805 J200.2@10.16,2.54
  Bottom Layer w0.15: v1(8.515,7.675) 8.515,6.05 10.16,4.405 J200.2@10.16,2.54
NC: J200.1
NetC102_1: C102.1 U102.6 | length 1.3
  Top-Layer w0.2: U102.6@15.115,14.725 15.115,14.975 C102.1@15.865,15.725
NetD100_1: D100.1 R107.1 | length 3.9
  Top-Layer w0.15: D100.1@7.071,4.6 7.768,5.297 9.669,5.297 R107.1@10.39,4.575
NetD200_1: D200.1 R203.2 | length 1.2
  Top-Layer w0.175: D200.1@74.221,11.006 74.571,10.656 R203.2@75.3,10.656
NetJ209_2: J209.2 XC200.1 | length 1.5
  Top-Layer w0.15: J209.2@39.097,10.428 39.097,11.306 XC200.1@39.572,11.781
NetQ101_3: Q101.3 R110.1 | length 1
  Top-Layer w0.15: R110.1@8.674,13.7 8.815,13.559 Q101.3@8.815,12.8
NetR202_2: R202.2 SW200.3 SW200.4 | length 7.5
  Top-Layer w0.175: R202.2@76.405,10.656 78.385,10.656 ; SW200.4@78.391,7.41 SW200.3@78.391,12.91
PA0_UART0_TX: J200.7 U200.44 | length 27.7
  Top-Layer w0.175: J200.7@22.86,2.54 25.472,5.152 47.443,5.152 47.879,5.588 47.879,6.178 U200.44@48.449,6.748
PA1_UART0_RX: J200.8 U200.45 | length 25.2
  Top-Layer w0.175: J200.8@25.4,2.743 27.407,4.75 47.676,4.75 48.26,5.334 48.26,5.852 U200.45@48.802,6.395
PA2: J200.36 U200.46 | length 17.3
  Top-Layer w0.15: U200.46@49.156,6.041 49.915,6.8 49.915,7.88 50.777,8.742 v1(50.777,11.564)
  Bottom Layer w0.15: v1(50.777,11.564) 52.09,11.564 53.108,12.582 54.472,12.582 58.42,16.529 J200.36@58.42,17.983
PA3: J200.37 U200.47 | length 15.5
  Top-Layer w0.15: U200.47@49.51,5.688 50.215,6.393 50.215,7.756 51.675,9.216 v1(51.675,12.25)
  Bottom Layer w0.15: v1(51.675,12.25) 52.329,12.904 54,12.904 55.88,14.785 J200.37@55.88,17.577
PA4_SPI0_MOSI: J200.11 U200.48 | length 20.6
  Top-Layer w0.175: U200.48@49.863,5.334 50.752,6.223 v1(50.8,6.223)
  Bottom Layer w0.175: J200.11@33.02,2.54 35.68,5.2 49.777,5.2 v1(50.8,6.223)
PA5_SPI0_MISO: J200.12 U200.1 | length 17.3
  Top-Layer w0.175: J200.12@35.56,2.743 37.067,4.25 50.653,4.25 U200.1@51.737,5.334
